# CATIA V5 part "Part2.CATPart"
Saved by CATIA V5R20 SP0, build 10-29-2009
Part number: Part2
Bounding box of the stored display mesh (mm): x 141.153 to 191.522, y -25.184 to 25.184, z 12.7 to 15.875
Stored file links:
  C:\Users\TAK SYS\Desktop\Part2.CATPart
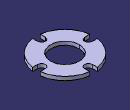
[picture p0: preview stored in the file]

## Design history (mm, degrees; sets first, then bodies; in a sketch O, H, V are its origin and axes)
Body1 (main body)
  DatumSurface1
  Sketch1 on face of DatumSurface1, origin (0, 0, 12.7), H (1, 0, 0), V (0, 1, 0)
    circle A1 centre (166.3377, 0) radius 25.4
    circle A2 centre (166.3377, 0) radius 12.7
    arc A3 centre (166.3377, 20.6502) radius 3.302 from (163.0357, 20.6502) to (169.6397, 20.6502) ccw
    line L1 (163.0357, 20.6502) -> (163.0357, 27.7231)
    line L2 (169.6397, 20.6502) -> (169.6397, 27.7231)
    line L3 (169.6397, 27.7231) -> (163.0357, 27.7231)
    line L4 (145.6875, -3.302) -> (138.6146, -3.302)
    line L5 (138.6146, 3.302) -> (138.6146, -3.302)
    line L6 (145.6875, 3.302) -> (138.6146, 3.302)
    arc A4 centre (145.6875, 0) radius 3.302 from (145.6875, -3.302) to (145.6875, 3.302) ccw
    line L7 (169.6397, -20.6502) -> (169.6397, -27.7231)
    line L8 (163.0357, -27.7231) -> (169.6397, -27.7231)
    line L9 (163.0357, -20.6502) -> (163.0357, -27.7231)
    arc A5 centre (166.3377, -20.6502) radius 3.302 from (169.6397, -20.6502) to (163.0357, -20.6502) ccw
    line L10 (186.9879, 3.302) -> (194.0609, 3.302)
    line L11 (194.0609, -3.302) -> (194.0609, 3.302)
    line L12 (186.9879, -3.302) -> (194.0609, -3.302)
    arc A6 centre (186.9879, 0) radius 3.302 from (186.9879, 3.302) to (186.9879, -3.302) ccw
    radius A1 = 25.4
    radius A2 = 12.7
    radius A3 = 3.302
  Pad1: profile Sketch1.A2, length 3.175
  Pocket1: profile Sketch1.L1, length 3.175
